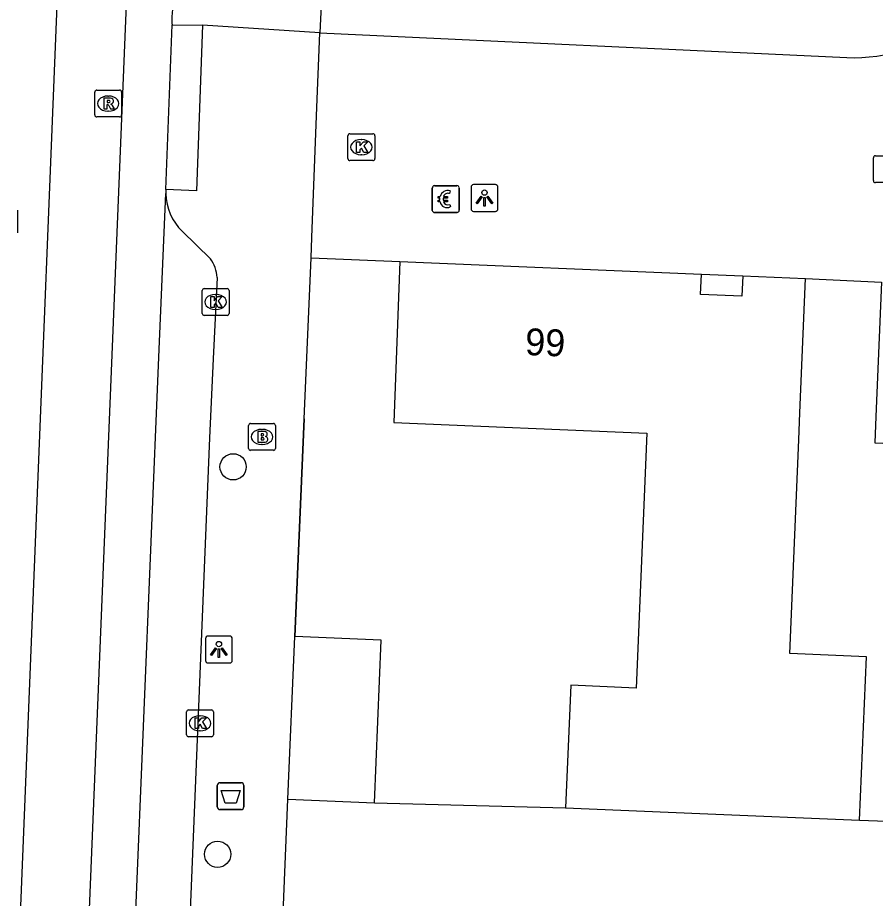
# Model space of a CAD drawing. Extents: x 160787 to 161428, y 386828 to 387483.
# Drawn here: x 161292.92 to 161324.86, y 386925.55 to 386958.33 of the extents above; entities that cross this region are included whole.
import ezdxf

# ---------------------------------------------------------------- set-up
doc = ezdxf.new("R2010")
doc.units = 0
for name, color, linetype in [('IMGEO_Afvalbak', 7, 'Continuous'), ('IMGEO_Betaalautomaat', 7, 'Continuous'), ('IMGEO_Boom', 7, 'Continuous'), ('IMGEO_Brandkraan', 7, 'Continuous'), ('IMGEO_Groenvoorziening', 7, 'Continuous'), ('IMGEO_Kolk', 7, 'Continuous'), ('IMGEO_Lichtpunt', 7, 'Continuous'), ('IMGEO_Muur', 7, 'Continuous'), ('IMGEO_Pand', 7, 'Continuous'), ('IMGEO_Pand_nummerreeks', 7, 'Continuous'), ('IMGEO_Rijbaan_lokaal_gesloten', 7, 'Continuous'), ('IMGEO_Rijbaan_lokaal_open', 7, 'Continuous'), ('IMGEO_Rioolput', 7, 'Continuous'), ('IMGEO_Voetpad_open', 7, 'Continuous')]:
    doc.layers.add(name, color=color, linetype=linetype)

msp = doc.modelspace()

# ---------------------------------------------------------------- linework, layer by layer
at = {"layer": 'IMGEO_Afvalbak'}
for p, q in [((161300.455, 386929.852), (161301.245, 386929.852)), ((161301.245, 386929.852), (161300.455, 386929.852)), ((161300.355, 386928.952), (161300.355, 386929.752)), ((161300.355, 386929.752), (161300.355, 386928.952)), ((161301.345, 386929.752), (161301.345, 386928.952)), ((161301.345, 386928.952), (161301.345, 386929.752)), ((161301.245, 386928.852), (161300.455, 386928.852)), ((161300.455, 386928.852), (161301.245, 386928.852))]:
    msp.add_line(p, q, dxfattribs=at)
msp.add_lwpolyline([(161300.498, 386929.566), (161301.202, 386929.566), (161301.053, 386929.096), (161300.647, 386929.096), (161300.498, 386929.566)], dxfattribs=at)
for centre, start, end in [((161300.455, 386929.752), 90, 180), ((161300.455, 386929.752), 90, 180), ((161301.245, 386929.752), 0, 90), ((161301.245, 386929.752), 360, 90), ((161300.455, 386928.952), 180, 270), ((161300.455, 386928.952), 180, 270), ((161301.245, 386928.952), 270, 0), ((161301.245, 386928.952), 270, 0)]:
    msp.add_arc(centre, 0.1, start, end, dxfattribs=at)
at = {"layer": 'IMGEO_Betaalautomaat'}
for p, q in [((161308.362, 386951.154), (161308.362, 386951.995)), ((161308.362, 386951.995), (161308.362, 386951.154)), ((161308.437, 386952.078), (161309.278, 386952.078)), ((161309.278, 386952.078), (161308.437, 386952.078)), ((161309.024, 386951.883), (161309.007, 386951.783)), ((161309.361, 386952.004), (161309.361, 386951.163)), ((161309.361, 386951.163), (161309.361, 386952.004)), ((161308.645, 386951.542), (161308.645, 386951.61)), ((161308.766, 386951.61), (161308.766, 386951.542)), ((161309.011, 386951.377), (161309.033, 386951.29)), ((161309.287, 386951.079), (161308.446, 386951.079)), ((161308.446, 386951.079), (161309.287, 386951.079))]:
    msp.add_line(p, q, dxfattribs=at)
for points in [[(161308.645, 386951.61), (161308.576, 386951.61), (161308.576, 386951.679), (161308.655, 386951.679)], [(161308.65, 386951.473), (161308.576, 386951.473), (161308.576, 386951.542), (161308.645, 386951.542)], [(161308.777, 386951.679), (161308.924, 386951.679), (161308.924, 386951.61), (161308.766, 386951.61)], [(161308.766, 386951.542), (161308.924, 386951.542), (161308.924, 386951.473), (161308.78, 386951.473)]]:
    msp.add_lwpolyline(points, dxfattribs=at)
for centre, radius, start, end in [((161308.44, 386952.001), 0.0779, 92.4484, 184.2845), ((161308.44, 386952.001), 0.0779, 92.4484, 184.2845), ((161308.938, 386951.603), 0.293, 73.014, 165.0139), ((161309.284, 386952.001), 0.0779, 2.4484, 94.2845), ((161309.284, 386952.001), 0.0779, 2.4484, 94.2845), ((161308.911, 386951.528), 0.267, 191.8096, 297.0389), ((161308.944, 386951.616), 0.179, 69.3236, 159.5683), ((161308.944, 386951.543), 0.179, 202.7625, 291.8693), ((161308.44, 386951.157), 0.0779, 182.4484, 274.2845), ((161308.44, 386951.157), 0.0779, 182.4484, 274.2845), ((161309.284, 386951.157), 0.0779, 272.4484, 4.2845), ((161309.284, 386951.157), 0.0779, 272.4484, 4.2845)]:
    msp.add_arc(centre, radius, start, end, dxfattribs=at)
at = {"layer": 'IMGEO_Boom'}
for centre in [(161300.945, 386941.612), (161300.368, 386927.189)]:
    msp.add_circle(centre, 0.489, dxfattribs=at)
at = {"layer": 'IMGEO_Brandkraan'}
for p, q in [((161301.519, 386942.3), (161301.519, 386943.152)), ((161301.594, 386943.226), (161302.446, 386943.226)), ((161302.007, 386943.006), (161302.032, 386943.006)), ((161302.52, 386943.152), (161302.52, 386942.3)), ((161302.03, 386942.446), (161302.005, 386942.446)), ((161302.446, 386942.226), (161301.594, 386942.226))]:
    msp.add_line(p, q, dxfattribs=at)
for points in [[(161301.519, 386942.3), (161301.519, 386943.152)], [(161301.594, 386943.226), (161302.446, 386943.226)], [(161302.52, 386943.152), (161302.52, 386942.3)], [(161301.867, 386942.926), (161301.867, 386942.526), (161302.08, 386942.526)], [(161302.098, 386942.926), (161301.867, 386942.926)], [(161302.046, 386942.845), (161301.992, 386942.845), (161301.992, 386942.769)], [(161301.992, 386942.769), (161302.045, 386942.769)], [(161302.054, 386942.693), (161301.992, 386942.693), (161301.992, 386942.612)], [(161301.992, 386942.612), (161302.054, 386942.612)], [(161302.446, 386942.226), (161301.594, 386942.226)]]:
    msp.add_lwpolyline(points, dxfattribs=at)
for centre, radius, start, end in [((161301.596, 386943.15), 0.0765, 91.552, 178.448), ((161301.596, 386943.15), 0.0765, 91.552, 178.448), ((161302.444, 386943.15), 0.0765, 1.552, 88.448), ((161302.444, 386943.15), 0.0765, 1.552, 88.448), ((161302.047, 386942.807), 0.0379, 267.8285, 90.9355), ((161302.055, 386942.652), 0.0404, 269.8759, 90.5077), ((161302.102, 386942.781), 0.145, 59.4692, 91.5367), ((161302.127, 386942.828), 0.0922, 285.5137, 58.1501), ((161302.132, 386942.636), 0.105, 301.3115, 78.989), ((161301.596, 386942.302), 0.0765, 181.552, 268.448), ((161301.596, 386942.302), 0.0765, 181.552, 268.448), ((161302.086, 386942.777), 0.251, 268.6676, 293.5347), ((161302.444, 386942.302), 0.0765, 271.552, 358.448), ((161302.444, 386942.302), 0.0765, 271.552, 358.448)]:
    msp.add_arc(centre, radius, start, end, dxfattribs=at)
for centre, major_axis, ratio, start_param, end_param in [((161302.006, 386942.726), (-0.387, 0.002), 0.722429, 4.712389, 7.853982), ((161302.031, 386942.726), (-0.39, 0.002), 0.717154, 1.570796, 4.712389)]:
    msp.add_ellipse(centre, major_axis=major_axis, ratio=ratio, start_param=start_param, end_param=end_param, dxfattribs=at)
at = {"layer": 'IMGEO_Groenvoorziening'}
for points in [[(161306.205, 386929.1), (161313.324, 386928.917)], [(161324.27, 386928.456), (161331.342, 386928.203)]]:
    msp.add_lwpolyline(points, dxfattribs=at)
at = {"layer": 'IMGEO_Kolk'}
for p, q in [((161305.22, 386953.086), (161305.22, 386953.938)), ((161305.295, 386954.012), (161306.147, 386954.012)), ((161305.708, 386953.792), (161305.733, 386953.792)), ((161306.221, 386953.938), (161306.221, 386953.086)), ((161305.731, 386953.232), (161305.706, 386953.232)), ((161324.784, 386952.265), (161324.784, 386953.117)), ((161324.859, 386953.191), (161325.711, 386953.191)), ((161306.147, 386953.012), (161305.295, 386953.012)), ((161325.711, 386952.191), (161324.859, 386952.191)), ((161292.92, 386951.171), (161292.92, 386950.319)), ((161299.868, 386948.248), (161300.72, 386948.248)), ((161299.793, 386947.322), (161299.793, 386948.174)), ((161300.281, 386948.028), (161300.306, 386948.028)), ((161300.794, 386948.174), (161300.794, 386947.322)), ((161300.72, 386947.248), (161299.868, 386947.248)), ((161300.304, 386947.468), (161300.279, 386947.468)), ((161299.21, 386931.639), (161299.21, 386932.491)), ((161299.285, 386932.565), (161300.137, 386932.565)), ((161300.211, 386932.491), (161300.211, 386931.639)), ((161299.698, 386932.345), (161299.723, 386932.345)), ((161300.137, 386931.565), (161299.285, 386931.565)), ((161299.721, 386931.785), (161299.696, 386931.785))]:
    msp.add_line(p, q, dxfattribs=at)
for points in [[(161305.22, 386953.086), (161305.22, 386953.938)], [(161305.295, 386954.012), (161306.147, 386954.012)], [(161306.221, 386953.938), (161306.221, 386953.086)], [(161305.541, 386953.712), (161305.664, 386953.712), (161305.664, 386953.561), (161305.794, 386953.712), (161305.958, 386953.712), (161305.812, 386953.561), (161305.965, 386953.312), (161305.813, 386953.312), (161305.728, 386953.476), (161305.664, 386953.409), (161305.664, 386953.312), (161305.541, 386953.312), (161305.541, 386953.712)], [(161324.784, 386952.265), (161324.784, 386953.117)], [(161324.859, 386953.191), (161325.711, 386953.191)], [(161306.147, 386953.012), (161305.295, 386953.012)], [(161325.711, 386952.191), (161324.859, 386952.191)], [(161292.92, 386951.171), (161292.92, 386950.319)], [(161299.868, 386948.248), (161300.72, 386948.248)], [(161299.793, 386947.322), (161299.793, 386948.174)], [(161300.114, 386947.948), (161300.237, 386947.948), (161300.237, 386947.797), (161300.367, 386947.948), (161300.531, 386947.948), (161300.385, 386947.797), (161300.538, 386947.548), (161300.386, 386947.548), (161300.301, 386947.712), (161300.237, 386947.645), (161300.237, 386947.548), (161300.114, 386947.548), (161300.114, 386947.948)], [(161300.794, 386948.174), (161300.794, 386947.322)], [(161300.72, 386947.248), (161299.868, 386947.248)], [(161299.21, 386931.639), (161299.21, 386932.491)], [(161299.285, 386932.565), (161300.137, 386932.565)], [(161300.211, 386932.491), (161300.211, 386931.639)], [(161299.531, 386932.265), (161299.654, 386932.265), (161299.654, 386932.114), (161299.784, 386932.265), (161299.948, 386932.265), (161299.802, 386932.114), (161299.955, 386931.865), (161299.803, 386931.865), (161299.718, 386932.029), (161299.654, 386931.962), (161299.654, 386931.865), (161299.531, 386931.865), (161299.531, 386932.265)], [(161300.137, 386931.565), (161299.285, 386931.565)]]:
    msp.add_lwpolyline(points, dxfattribs=at)
for centre, start, end in [((161305.297, 386953.936), 91.552, 178.448), ((161305.297, 386953.936), 91.552, 178.448), ((161306.145, 386953.936), 1.552, 88.448), ((161306.145, 386953.936), 1.552, 88.448), ((161324.861, 386953.115), 91.552, 178.448), ((161324.861, 386953.115), 91.552, 178.448), ((161305.297, 386953.088), 181.552, 268.448), ((161305.297, 386953.088), 181.552, 268.448), ((161306.145, 386953.088), 271.552, 358.448), ((161306.145, 386953.088), 271.552, 358.448), ((161324.861, 386952.267), 181.552, 268.448), ((161324.861, 386952.267), 181.552, 268.448), ((161299.87, 386948.172), 91.552, 178.448), ((161299.87, 386948.172), 91.552, 178.448), ((161300.718, 386948.172), 1.552, 88.448), ((161300.718, 386948.172), 1.552, 88.448), ((161299.87, 386947.324), 181.552, 268.448), ((161299.87, 386947.324), 181.552, 268.448), ((161300.718, 386947.324), 271.552, 358.448), ((161300.718, 386947.324), 271.552, 358.448), ((161299.287, 386932.489), 91.552, 178.448), ((161299.287, 386932.489), 91.552, 178.448), ((161300.135, 386932.489), 1.552, 88.448), ((161300.135, 386932.489), 1.552, 88.448), ((161299.287, 386931.641), 181.552, 268.448), ((161299.287, 386931.641), 181.552, 268.448), ((161300.135, 386931.641), 271.552, 358.448), ((161300.135, 386931.641), 271.552, 358.448)]:
    msp.add_arc(centre, 0.0765, start, end, dxfattribs=at)
for centre, major_axis, ratio, start_param, end_param in [((161305.707, 386953.512), (-0.387, 0.002), 0.722429, 4.712389, 7.853982), ((161305.732, 386953.512), (-0.39, 0.002), 0.717154, 1.570796, 4.712389), ((161300.28, 386947.748), (-0.387, 0.002), 0.722429, 4.712389, 7.853982), ((161300.305, 386947.748), (-0.39, 0.002), 0.717154, 1.570796, 4.712389), ((161299.697, 386932.065), (-0.387, 0.002), 0.722429, 4.712389, 7.853982), ((161299.722, 386932.065), (-0.39, 0.002), 0.717154, 1.570796, 4.712389)]:
    msp.add_ellipse(centre, major_axis=major_axis, ratio=ratio, start_param=start_param, end_param=end_param, dxfattribs=at)
at = {"layer": 'IMGEO_Lichtpunt'}
for p, q in [((161309.806, 386952.024), (161309.806, 386951.217)), ((161309.806, 386952.024), (161309.806, 386951.217)), ((161310.708, 386952.119), (161309.9, 386952.119)), ((161310.708, 386952.119), (161309.9, 386952.119)), ((161310.802, 386951.217), (161310.802, 386952.024)), ((161310.802, 386951.217), (161310.802, 386952.024)), ((161309.9, 386951.123), (161310.708, 386951.123)), ((161309.9, 386951.123), (161310.708, 386951.123)), ((161299.916, 386935.215), (161299.916, 386934.408)), ((161299.916, 386935.215), (161299.916, 386934.408)), ((161300.818, 386935.31), (161300.01, 386935.31)), ((161300.818, 386935.31), (161300.01, 386935.31)), ((161300.912, 386934.408), (161300.912, 386935.215)), ((161300.912, 386934.408), (161300.912, 386935.215)), ((161300.01, 386934.314), (161300.818, 386934.314)), ((161300.01, 386934.314), (161300.818, 386934.314))]:
    msp.add_line(p, q, dxfattribs=at)
for points in [[(161310.18, 386951.688), (161310.219, 386951.66), (161310.031, 386951.398), (161309.993, 386951.425), (161310.18, 386951.688)], [(161310.282, 386951.64), (161310.329, 386951.64), (161310.329, 386951.318), (161310.282, 386951.318), (161310.282, 386951.64)], [(161310.392, 386951.66), (161310.43, 386951.687), (161310.617, 386951.425), (161310.578, 386951.397), (161310.392, 386951.66)], [(161300.29, 386934.879), (161300.329, 386934.851), (161300.141, 386934.589), (161300.103, 386934.616), (161300.29, 386934.879)], [(161300.392, 386934.831), (161300.439, 386934.831), (161300.439, 386934.509), (161300.392, 386934.509), (161300.392, 386934.831)], [(161300.502, 386934.851), (161300.54, 386934.878), (161300.727, 386934.616), (161300.688, 386934.588), (161300.502, 386934.851)]]:
    msp.add_lwpolyline(points, dxfattribs=at)
for centre in [(161310.305, 386951.822), (161300.415, 386935.013)]:
    msp.add_circle(centre, 0.0994, dxfattribs=at)
for centre, start, end in [((161309.9, 386952.024), 90, 180), ((161309.9, 386952.024), 90, 180), ((161310.708, 386952.024), 0, 90), ((161310.708, 386952.024), 0, 90), ((161309.9, 386951.217), 180, 270), ((161309.9, 386951.217), 180, 270), ((161310.708, 386951.217), 270, 0), ((161310.708, 386951.217), 270, 360), ((161300.01, 386935.215), 90, 180), ((161300.01, 386935.215), 90, 180), ((161300.818, 386935.215), 0, 90), ((161300.818, 386935.215), 0, 90), ((161300.01, 386934.408), 180, 270), ((161300.01, 386934.408), 180, 270), ((161300.818, 386934.408), 270, 0), ((161300.818, 386934.408), 270, 360)]:
    msp.add_arc(centre, 0.0946, start, end, dxfattribs=at)
at = {"layer": 'IMGEO_Muur'}
msp.add_lwpolyline([(161303.59, 386943.404), (161303.238, 386935.299)], dxfattribs=at)
at = {"layer": 'IMGEO_Pand'}
for points in [[(161307.152, 386949.254), (161306.923, 386943.264), (161316.348, 386942.867), (161315.949, 386933.376), (161313.516, 386933.478), (161313.324, 386928.917)], [(161307.152, 386949.254), (161318.382, 386948.782)], [(161319.921, 386948.717), (161319.89, 386947.969), (161318.351, 386948.033), (161318.382, 386948.782)], [(161319.921, 386948.717), (161322.258, 386948.619)], [(161324.27, 386928.456), (161324.526, 386934.537), (161321.671, 386934.657), (161322.006, 386942.621), (161322.048, 386943.624), (161322.258, 386948.619)], [(161325.088, 386948.483), (161324.878, 386943.488), (161324.836, 386942.502), (161334.304, 386942.104), (161333.904, 386932.585), (161331.53, 386932.684), (161331.342, 386928.203)], [(161302.982, 386929.236), (161303.238, 386935.299)], [(161306.205, 386929.1), (161306.461, 386935.163), (161303.238, 386935.299)], [(161302.982, 386929.236), (161306.205, 386929.1)], [(161313.324, 386928.917), (161318.32, 386928.707), (161324.27, 386928.456)]]:
    msp.add_lwpolyline(points, dxfattribs=at)
at = {"layer": 'IMGEO_Rijbaan_lokaal_gesloten'}
for points in [[(161300.938, 387054.844), (161299.353, 387017.413), (161294.661, 386902.681)], [(161295.454, 386994.199), (161295.632, 386989.894), (161292.315, 386907.717)], [(161298.441, 386951.94), (161298.669, 386958.063)], [(161296.461, 386904.443), (161298.179, 386945.692), (161298.439, 386951.784)]]:
    msp.add_lwpolyline(points, dxfattribs=at)
for centre, radius, start, end in [((161300.426, 386958.264), 1.768, 168.84, 186.5198), ((161299.96, 386951.843), 1.522, 176.3284, 182.2026)]:
    msp.add_arc(centre, radius, start, end, dxfattribs=at)
at = {"layer": 'IMGEO_Rijbaan_lokaal_open'}
for points in [[(161303.85, 386949.393), (161303.879, 386950.146), (161304.054, 386954.684), (161304.173, 386957.768)], [(161304.173, 386957.768), (161323.794, 386956.846)], [(161303.85, 386949.393), (161307.152, 386949.254)], [(161318.382, 386948.782), (161319.921, 386948.717)], [(161322.258, 386948.619), (161325.088, 386948.483)]]:
    msp.add_lwpolyline(points, dxfattribs=at)
msp.add_arc((161324.056, 386962.441), 5.601, 267.3199, 358.2336, dxfattribs=at)
at = {"layer": 'IMGEO_Rioolput'}
for p, q in [((161295.793, 386954.71), (161295.793, 386955.562)), ((161295.868, 386955.636), (161296.72, 386955.636)), ((161296.281, 386955.416), (161296.306, 386955.416)), ((161296.794, 386955.562), (161296.794, 386954.71)), ((161296.304, 386954.856), (161296.279, 386954.856)), ((161296.72, 386954.636), (161295.868, 386954.636))]:
    msp.add_line(p, q, dxfattribs=at)
for points in [[(161295.793, 386954.71), (161295.793, 386955.562)], [(161295.868, 386955.636), (161296.72, 386955.636)], [(161296.794, 386955.562), (161296.794, 386954.71)], [(161296.382, 386955.334), (161296.13, 386955.336), (161296.13, 386954.936)], [(161296.13, 386954.936), (161296.254, 386954.936), (161296.254, 386955.098), (161296.265, 386955.098)], [(161296.308, 386955.255), (161296.254, 386955.255), (161296.254, 386955.174)], [(161296.254, 386955.174), (161296.306, 386955.174)], [(161296.312, 386955.069), (161296.383, 386954.936), (161296.523, 386954.936), (161296.458, 386955.062)], [(161296.72, 386954.636), (161295.868, 386954.636)]]:
    msp.add_lwpolyline(points, dxfattribs=at)
for centre, radius, start, end in [((161295.87, 386955.56), 0.0765, 91.552, 178.448), ((161295.87, 386955.56), 0.0765, 91.552, 178.448), ((161296.718, 386955.56), 0.0765, 1.552, 88.448), ((161296.718, 386955.56), 0.0765, 1.552, 88.448), ((161296.264, 386955.045), 0.0533, 26.0293, 88.6989), ((161296.29, 386955.363), 0.19, 274.7715, 282.9687), ((161296.314, 386955.159), 0.0964, 77.0061, 93.1865), ((161296.328, 386955.216), 0.0378, 276.6634, 79.6772), ((161296.381, 386955.224), 0.109, 350.3612, 89.416), ((161296.379, 386955.224), 0.112, 277.5842, 350.9817), ((161296.363, 386955.009), 0.108, 29.5134, 73.7905), ((161295.87, 386954.712), 0.0765, 181.552, 268.448), ((161295.87, 386954.712), 0.0765, 181.552, 268.448), ((161296.718, 386954.712), 0.0765, 271.552, 358.448), ((161296.718, 386954.712), 0.0765, 271.552, 358.448)]:
    msp.add_arc(centre, radius, start, end, dxfattribs=at)
for centre, major_axis, ratio, start_param, end_param in [((161296.28, 386955.136), (-0.387, 0.002), 0.722429, 4.712389, 7.853982), ((161296.305, 386955.136), (-0.39, 0.002), 0.717154, 1.570796, 4.712389)]:
    msp.add_ellipse(centre, major_axis=major_axis, ratio=ratio, start_param=start_param, end_param=end_param, dxfattribs=at)
at = {"layer": 'IMGEO_Voetpad_open'}
for points in [[(161304.643, 386967.566), (161304.173, 386957.768)], [(161299.805, 386958.056), (161299.575, 386951.886), (161298.441, 386951.94)], [(161298.669, 386958.063), (161299.805, 386958.056)], [(161304.173, 386957.768), (161299.805, 386958.056)], [(161299.044, 386950.382), (161300.099, 386949.355)], [(161303.238, 386935.299), (161303.59, 386943.404), (161303.85, 386949.393)], [(161300.345, 386948.662), (161300.203, 386945.628), (161300.066, 386942.692), (161298.664, 386908.404), (161298.617, 386907.135)], [(161302.493, 386917.433), (161302.982, 386929.236)]]:
    msp.add_lwpolyline(points, dxfattribs=at)
for centre, radius, start, end in [((161300.483, 386951.834), 2.044, 181.4128, 225.2702), ((161299.073, 386948.601), 1.273, 2.7573, 36.3303)]:
    msp.add_arc(centre, radius, start, end, dxfattribs=at)

# ---------------------------------------------------------------- texts
at = {"layer": 'IMGEO_Pand_nummerreeks'}
msp.add_text('99', height=1, rotation=357.5933, dxfattribs=at).set_placement((161311.804, 386945.776))

doc.saveas('drawing.dxf')
